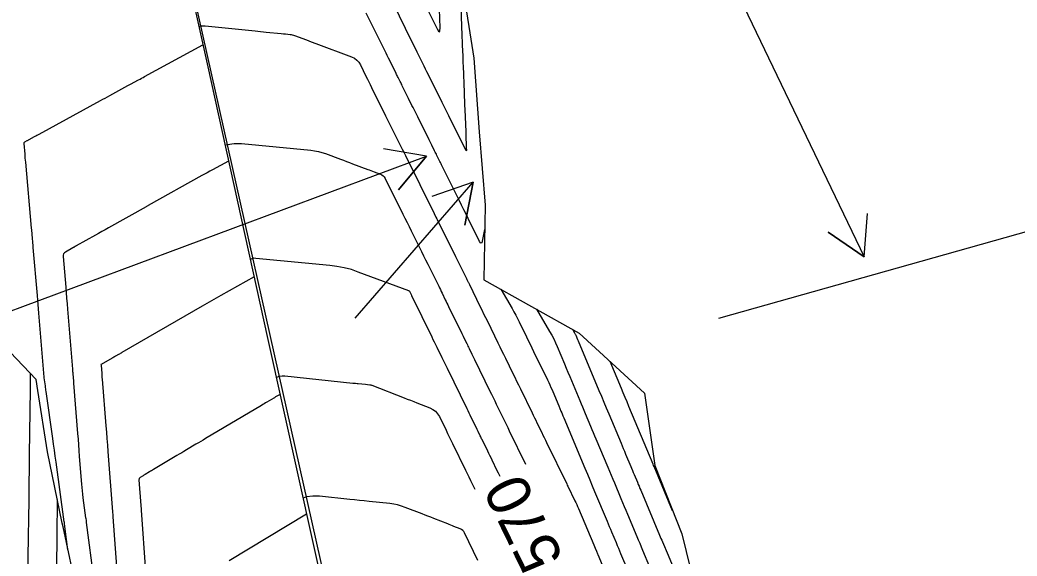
# Model space of a CAD drawing. Extents: x 954385 to 988206, y 1868364 to 1924553.
# Drawn here: x 957911.1 to 958048.1, y 1919236.3 to 1919309.9 of the extents above; entities that cross this region are included whole.
import ezdxf

# ---------------------------------------------------------------- set-up
doc = ezdxf.new("R2010")
doc.units = 0
for name, color, linetype in [('Default', 7, 'Continuous'), ('Ex_Contour Labels', 7, 'Continuous'), ('Ex_Major Contours', 7, 'Continuous'), ('Ex_Minor Contours', 7, 'Continuous'), ('Perimeter', 7, 'Continuous'), ('Proposed Cut', 7, 'Continuous'), ('Proposed Fill', 7, 'Continuous'), ('Slopes', 7, 'Continuous')]:
    doc.layers.add(name, color=color, linetype=linetype)

msp = doc.modelspace()

# ---------------------------------------------------------------- linework, layer by layer
for points in [[(957917.69, 1919237.11), (957917.27, 1919240.31), (957917.26, 1919240.36), (957917.21, 1919240.72), (957917.2, 1919240.78), (957917.2, 1919240.84), (957917.19, 1919240.91), (957917.18, 1919240.97), (957916.06, 1919249.16), (957915.94, 1919249.97), (957915.83, 1919250.78), (957915.72, 1919251.6), (957915.6, 1919252.41), (957914.69, 1919258.86), (957914.66, 1919259.05), (957914.64, 1919259.23), (957914.61, 1919259.42), (957914.58, 1919259.61), (957914.42, 1919260.74), (957914.41, 1919260.8), (957914.41, 1919260.81), (957914.41, 1919260.82), (957914.41, 1919260.83), (957914.41, 1919260.84), (957913.7, 1919269.6), (957913.65, 1919270.2), (957913.6, 1919270.81), (957913.55, 1919271.41), (957913.5, 1919272.02), (957912.93, 1919278.64), (957912.93, 1919278.69), (957912.92, 1919278.75), (957912.92, 1919278.8), (957912.91, 1919278.85), (957912.77, 1919280.44), (957912.75, 1919280.65), (957912.74, 1919280.86), (957912.72, 1919281.07), (957912.7, 1919281.28), (957911.88, 1919290.36), (957911.86, 1919290.63), (957911.83, 1919290.9), (957911.81, 1919291.17), (957911.79, 1919291.44), (957911.66, 1919292.91), (957911.66, 1919292.99), (957911.68, 1919293.05), (957911.72, 1919293.11), (957911.78, 1919293.15), (957912.07, 1919293.31), (957912.14, 1919293.35), (957912.21, 1919293.38), (957912.28, 1919293.42), (957912.35, 1919293.46), (957913.11, 1919293.88), (957913.26, 1919293.96), (957913.41, 1919294.05), (957913.56, 1919294.13), (957913.71, 1919294.21), (957922.16, 1919298.81), (957922.48, 1919298.99), (957922.79, 1919299.16), (957923.11, 1919299.33), (957923.42, 1919299.5), (957925.9, 1919300.87), (957926, 1919300.92), (957926.1, 1919300.97), (957926.2, 1919301.03), (957926.3, 1919301.08), (957927.38, 1919301.66), (957927.59, 1919301.77), (957927.8, 1919301.89), (957928.01, 1919302), (957928.22, 1919302.12), (957936.23, 1919306.49)], [(957939.75, 1919290.51), (957937.56, 1919289.31), (957937.19, 1919289.11), (957936.82, 1919288.91), (957936.46, 1919288.71), (957936.09, 1919288.51), (957928.72, 1919284.39), (957928.67, 1919284.37), (957928.49, 1919284.27), (957928.41, 1919284.22), (957923.25, 1919281.33), (957922.8, 1919281.08), (957922.35, 1919280.83), (957921.9, 1919280.57), (957921.45, 1919280.32), (957918.81, 1919278.84), (957918.78, 1919278.82), (957918.74, 1919278.8), (957918.71, 1919278.78), (957918.67, 1919278.75), (957918.52, 1919278.67), (957918.49, 1919278.65), (957918.45, 1919278.63), (957918.42, 1919278.61), (957918.38, 1919278.59), (957917.35, 1919278.01), (957917.19, 1919277.89), (957917.08, 1919277.75), (957917.03, 1919277.58), (957917.02, 1919277.38), (957917.38, 1919273.2), (957917.44, 1919272.44), (957917.51, 1919271.67), (957917.57, 1919270.9), (957917.63, 1919270.14), (957918.3, 1919261.93), (957918.31, 1919261.77), (957918.32, 1919261.61), (957918.34, 1919261.45), (957918.35, 1919261.29), (957918.43, 1919260.27), (957918.44, 1919260.14), (957918.44, 1919260.08), (957918.45, 1919260.01), (957919.01, 1919253.1), (957919.07, 1919252.31), (957919.13, 1919251.52), (957919.19, 1919250.73), (957919.25, 1919249.94), (957919.55, 1919246.12), (957919.59, 1919245.66), (957919.63, 1919245.19), (957919.68, 1919244.73), (957919.74, 1919244.27), (957920.12, 1919241.52), (957920.13, 1919241.47), (957920.18, 1919241.07), (957920.19, 1919241.02), (957920.2, 1919240.97), (957920.2, 1919240.91), (957920.21, 1919240.86), (957921.26, 1919232.87)], [(957943.26, 1919274.6), (957938.68, 1919272.02), (957938.04, 1919271.66), (957937.41, 1919271.3), (957936.77, 1919270.93), (957936.13, 1919270.57), (957925.09, 1919264.2), (957924.98, 1919264.13), (957924.87, 1919264.07), (957924.76, 1919264), (957924.65, 1919263.94), (957924.2, 1919263.69), (957924.09, 1919263.62), (957923.98, 1919263.56), (957923.87, 1919263.49), (957923.76, 1919263.43), (957922.24, 1919262.55), (957922.23, 1919262.54), (957922.23, 1919262.54), (957922.22, 1919262.54), (957922.23, 1919262.46), (957922.32, 1919261.32), (957922.33, 1919261.13), (957922.35, 1919260.94), (957922.36, 1919260.76), (957922.38, 1919260.57), (957922.9, 1919254.15), (957922.97, 1919253.26), (957923.04, 1919252.38), (957923.11, 1919251.5), (957923.17, 1919250.62), (957923.81, 1919242.33), (957923.81, 1919242.29), (957923.84, 1919241.89), (957923.85, 1919241.83), (957923.85, 1919241.77), (957923.85, 1919241.72), (957923.86, 1919241.66), (957924.48, 1919232.92)], [(957946.83, 1919258.46), (957946.31, 1919258.16), (957946.22, 1919258.11), (957946.14, 1919258.06), (957946.05, 1919258), (957945.96, 1919257.95), (957945.02, 1919257.39), (957944.83, 1919257.28), (957944.64, 1919257.17), (957944.46, 1919257.06), (957944.27, 1919256.95), (957936.59, 1919252.39), (957936.26, 1919252.19), (957935.93, 1919252), (957935.6, 1919251.8), (957935.27, 1919251.61), (957933.96, 1919250.82), (957933.63, 1919250.62), (957933.31, 1919250.43), (957932.98, 1919250.23), (957932.65, 1919250.04), (957929.44, 1919248.13), (957929.31, 1919248.05), (957929.18, 1919247.97), (957929.05, 1919247.89), (957928.91, 1919247.81), (957928.3, 1919247.44), (957928.21, 1919247.39), (957928.12, 1919247.34), (957928.04, 1919247.29), (957927.95, 1919247.23), (957927.6, 1919247.03), (957927.53, 1919246.97), (957927.48, 1919246.9), (957927.45, 1919246.82), (957927.44, 1919246.72), (957927.71, 1919243.2), (957927.72, 1919243.15), (957927.75, 1919242.75), (957927.75, 1919242.69), (957927.75, 1919242.64), (957927.76, 1919242.59), (957927.76, 1919242.54), (957928.36, 1919234.15)], [(957939.85, 1919235.64), (957950.47, 1919242.04)]]:
    msp.add_lwpolyline(points)
at = {"layer": 'Default'}
msp.add_line((958200.6, 1918129.72), (957843.86, 1919719.4), dxfattribs=at)
at = {"layer": 'Ex_Major Contours'}
for points in [[(957966.83, 1919311.87), (957968.4, 1919308.69), (957968.6, 1919308.36), (957968.73, 1919308.26), (957968.8, 1919308.41), (957968.81, 1919308.8), (957968.71, 1919311.35)], [(957977.06, 1919247.16), (957977.01, 1919247.28), (957976.84, 1919247.62), (957976.67, 1919247.97), (957975.96, 1919249.43), (957975.81, 1919249.73), (957975.66, 1919250.04), (957975.51, 1919250.35), (957975.36, 1919250.66), (957974.59, 1919252.25), (957974.52, 1919252.37), (957974.46, 1919252.5), (957974.4, 1919252.62), (957974.34, 1919252.75), (957974.04, 1919253.37), (957973.91, 1919253.62), (957973.85, 1919253.75), (957973.1, 1919255.28), (957972.96, 1919255.58), (957972.81, 1919255.88), (957972.67, 1919256.18), (957972.52, 1919256.47), (957969.82, 1919262.02), (957969.64, 1919262.38), (957969.47, 1919262.74), (957969.29, 1919263.1), (957969.11, 1919263.46), (957968.41, 1919264.89), (957968.23, 1919265.25), (957968.06, 1919265.61), (957967.88, 1919265.97), (957967.71, 1919266.33), (957964.97, 1919271.92), (957964.96, 1919271.95), (957964.95, 1919271.97), (957964.94, 1919272), (957964.93, 1919272.02), (957964.83, 1919272.22), (957964.68, 1919272.52), (957964.65, 1919272.57), (957964.6, 1919272.62), (957964.56, 1919272.65), (957964.5, 1919272.68), (957957.57, 1919275.26), (957956.62, 1919275.59), (957955.64, 1919275.85), (957954.65, 1919276.04), (957953.65, 1919276.17), (957943.49, 1919277.13), (957943.18, 1919277.16), (957943.14, 1919277.16), (957943.11, 1919277.16), (957943.07, 1919277.15), (957943.04, 1919277.13), (957942.78, 1919276.97), (957942.74, 1919276.95)], [(957987, 1919267.41), (957987.28, 1919266.92), (957987.33, 1919266.84), (957987.38, 1919266.75), (957987.42, 1919266.67), (957987.45, 1919266.58), (957987.69, 1919266.01), (957987.77, 1919265.83), (957990.64, 1919258.98), (957990.97, 1919258.19), (957991.31, 1919257.39), (957991.64, 1919256.59), (957991.98, 1919255.79), (957993.67, 1919251.76), (957993.83, 1919251.38), (957993.98, 1919251.01), (957994.14, 1919250.64), (957994.3, 1919250.26), (957995.01, 1919248.57), (957995.12, 1919248.3), (957995.24, 1919248.02), (957995.35, 1919247.75), (957995.47, 1919247.47), (957995.93, 1919246.38), (957996.04, 1919246.1), (957996.16, 1919245.83), (957996.27, 1919245.55), (957996.39, 1919245.28), (957998.97, 1919239.11), (957999.07, 1919238.88), (957999.16, 1919238.65), (957999.26, 1919238.43), (957999.36, 1919238.2), (958000.13, 1919236.37), (958003.01, 1919229.5)], [(957916.22, 1919244.01), (957916.16, 1919238.96), (957916.16, 1919238.7), (957916.15, 1919238.44), (957916.15, 1919238.18), (957916.15, 1919237.92), (957916.09, 1919233.61)]]:
    msp.add_lwpolyline(points, dxfattribs=at)
at = {"layer": 'Ex_Minor Contours'}
for points in [[(957971.55, 1919314.29), (957971.81, 1919307.77), (957971.82, 1919307.42), (957971.84, 1919307.07), (957971.85, 1919306.72), (957971.86, 1919306.37), (957971.92, 1919304.98), (957971.93, 1919304.64), (957971.95, 1919304.29), (957971.96, 1919303.94), (957971.98, 1919303.59), (957972.12, 1919299.94), (957972.14, 1919299.36), (957972.16, 1919298.77), (957972.19, 1919298.19), (957972.21, 1919297.61), (957972.33, 1919294.52), (957972.34, 1919294.32), (957972.34, 1919294.13), (957972.35, 1919293.93), (957972.36, 1919293.74), (957972.4, 1919292.76), (957972.41, 1919292.57), (957972.41, 1919292.39), (957972.43, 1919292.01), (957972.43, 1919291.94), (957972.41, 1919291.91), (957972.39, 1919291.93), (957972.35, 1919291.99), (957970.01, 1919296.71), (957969.78, 1919297.18), (957969.54, 1919297.64), (957969.31, 1919298.11), (957969.08, 1919298.57), (957967.2, 1919302.36), (957967.01, 1919302.75), (957966.82, 1919303.14), (957966.62, 1919303.52), (957966.43, 1919303.91), (957965.66, 1919305.47), (957965.28, 1919306.25), (957964.89, 1919307.02), (957962.39, 1919312.08)], [(957974.93, 1919281.09), (957974.6, 1919279.49), (957974.54, 1919279.29), (957974.46, 1919279.21), (957974.36, 1919279.26), (957974.25, 1919279.44), (957972.68, 1919282.6), (957972.38, 1919283.21), (957972.08, 1919283.82), (957971.77, 1919284.43), (957971.47, 1919285.04), (957969.01, 1919289.98), (957968.94, 1919290.14), (957968.86, 1919290.3), (957968.78, 1919290.46), (957968.7, 1919290.62), (957968.38, 1919291.27), (957968.3, 1919291.43), (957968.22, 1919291.59), (957968.14, 1919291.75), (957968.06, 1919291.91), (957967.67, 1919292.68), (957967.49, 1919293.04), (957967.31, 1919293.4), (957966.38, 1919295.28), (957966.22, 1919295.6), (957966.06, 1919295.92), (957965.9, 1919296.24), (957965.74, 1919296.56), (957965.11, 1919297.84), (957964.95, 1919298.16), (957964.79, 1919298.48), (957964.63, 1919298.8), (957964.47, 1919299.12), (957963.61, 1919300.86), (957963.54, 1919301), (957963.47, 1919301.14), (957963.4, 1919301.28), (957963.33, 1919301.42), (957963.05, 1919301.98), (957962.98, 1919302.12), (957962.91, 1919302.26), (957962.84, 1919302.4), (957962.78, 1919302.54), (957961.9, 1919304.31), (957961.73, 1919304.65), (957961.56, 1919304.99), (957961.39, 1919305.33), (957961.23, 1919305.67), (957958.68, 1919310.82)], [(957935.68, 1919308.98), (957935.68, 1919308.98), (957935.95, 1919309.06), (957936.23, 1919309.1), (957936.52, 1919309.09), (957943.39, 1919308.38), (957943.78, 1919308.34), (957944.16, 1919308.3), (957944.55, 1919308.26), (957944.94, 1919308.23), (957946.97, 1919308.03), (957947.28, 1919308), (957947.59, 1919307.97), (957948.21, 1919307.91), (957948.36, 1919307.89), (957948.51, 1919307.86), (957948.66, 1919307.82), (957948.8, 1919307.77), (957950.45, 1919307.15), (957951.09, 1919306.9), (957951.74, 1919306.66), (957956.66, 1919304.8), (957957.04, 1919304.62), (957957.36, 1919304.38), (957957.64, 1919304.08), (957957.86, 1919303.72), (957958.62, 1919302.16), (957958.82, 1919301.77), (957959.01, 1919301.38), (957959.2, 1919301), (957959.4, 1919300.61), (957961.33, 1919296.72), (957961.55, 1919296.26), (957961.78, 1919295.81), (957962.01, 1919295.35), (957962.23, 1919294.9), (957963.14, 1919293.07), (957963.36, 1919292.62), (957963.59, 1919292.16), (957963.82, 1919291.71), (957964.04, 1919291.25), (957968, 1919283.3), (957968.19, 1919282.91), (957968.24, 1919282.8), (957968.35, 1919282.59), (957968.4, 1919282.48), (957969.93, 1919279.41), (957970.18, 1919278.91), (957970.43, 1919278.4), (957970.68, 1919277.9), (957970.93, 1919277.4), (957972.34, 1919274.55), (957972.43, 1919274.38), (957972.51, 1919274.22), (957972.67, 1919273.89), (957972.71, 1919273.81), (957972.76, 1919273.72), (957972.8, 1919273.64), (957972.84, 1919273.56), (957974.29, 1919270.59), (957974.54, 1919270.07), (957974.8, 1919269.54), (957975.05, 1919269.02), (957975.31, 1919268.5), (957976.76, 1919265.54), (957977.01, 1919265.01), (957977.27, 1919264.49), (957977.53, 1919263.96), (957977.78, 1919263.44), (957978.81, 1919261.33), (957979.07, 1919260.81), (957979.32, 1919260.28), (957979.58, 1919259.76), (957979.84, 1919259.23), (957981.45, 1919255.93), (957981.61, 1919255.59), (957981.78, 1919255.25), (957981.95, 1919254.91), (957982.11, 1919254.57), (957982.78, 1919253.2), (957982.94, 1919252.86), (957983.11, 1919252.52), (957983.28, 1919252.18), (957983.44, 1919251.84), (957986.21, 1919246.17), (957986.29, 1919246.01), (957986.36, 1919245.86), (957987.34, 1919243.85), (957987.47, 1919243.59), (957987.59, 1919243.33), (957987.7, 1919243.07), (957987.82, 1919242.8), (957989.92, 1919237.79), (957990.01, 1919237.57), (957990.1, 1919237.35), (957990.29, 1919236.9), (957990.34, 1919236.79), (957990.38, 1919236.68), (957990.43, 1919236.57), (957990.47, 1919236.46), (957993.42, 1919229.47)], [(957939.27, 1919292.68), (957939.6, 1919292.78), (957940.54, 1919292.92), (957941.51, 1919292.9), (957951.07, 1919291.99), (957951.58, 1919291.92), (957952.09, 1919291.83), (957952.58, 1919291.7), (957953.06, 1919291.53), (957955.12, 1919290.76), (957955.54, 1919290.61), (957955.96, 1919290.45), (957956.38, 1919290.29), (957956.8, 1919290.14), (957958.87, 1919289.36), (957959.09, 1919289.28), (957959.3, 1919289.2), (957959.52, 1919289.12), (957959.74, 1919289.04), (957960.61, 1919288.71), (957960.82, 1919288.62), (957960.99, 1919288.49), (957961.14, 1919288.33), (957961.26, 1919288.13), (957963.7, 1919283.21), (957963.99, 1919282.64), (957964.27, 1919282.07), (957964.55, 1919281.5), (957964.84, 1919280.92), (957965.97, 1919278.64), (957966.26, 1919278.07), (957966.54, 1919277.5), (957966.82, 1919276.93), (957967.11, 1919276.36), (957968.62, 1919273.31), (957968.74, 1919273.08), (957968.85, 1919272.85), (957968.96, 1919272.61), (957969.08, 1919272.38), (957969.53, 1919271.45), (957969.65, 1919271.22), (957969.76, 1919270.99), (957969.87, 1919270.76), (957969.99, 1919270.52), (957971.81, 1919266.8), (957971.98, 1919266.46), (957972.14, 1919266.12), (957972.48, 1919265.44), (957972.56, 1919265.27), (957972.64, 1919265.1), (957972.72, 1919264.93), (957972.81, 1919264.76), (957973.19, 1919263.98), (957973.28, 1919263.8), (957973.37, 1919263.61), (957973.46, 1919263.43), (957973.55, 1919263.24), (957975.66, 1919258.92), (957975.88, 1919258.47), (957976.1, 1919258.01), (957976.32, 1919257.56), (957976.54, 1919257.1), (957977.43, 1919255.28), (957977.65, 1919254.83), (957977.88, 1919254.37), (957978.1, 1919253.92), (957978.32, 1919253.47), (957980.56, 1919248.87)], [(957977.14, 1919272.89), (957978.7, 1919270.25), (957978.95, 1919269.8), (957979.2, 1919269.36), (957979.44, 1919268.9), (957979.67, 1919268.44), (957980.69, 1919266.36), (957980.93, 1919265.86), (957981.17, 1919265.36), (957981.42, 1919264.86), (957981.66, 1919264.36), (957983.58, 1919260.44), (957983.74, 1919260.1), (957983.9, 1919259.76), (957984.05, 1919259.42), (957984.2, 1919259.07), (957984.98, 1919257.2), (957985.12, 1919256.87), (957985.42, 1919256.16), (957985.52, 1919255.91), (957985.7, 1919255.49), (957985.77, 1919255.32), (957985.8, 1919255.24), (957988.71, 1919248.3), (957989.05, 1919247.51), (957989.38, 1919246.71), (957989.72, 1919245.91), (957990.05, 1919245.11), (957991.75, 1919241.06), (957991.9, 1919240.69), (957992.06, 1919240.32), (957992.22, 1919239.95), (957992.37, 1919239.57), (957993, 1919238.09), (957993.15, 1919237.71), (957993.31, 1919237.34), (957993.47, 1919236.97), (957993.62, 1919236.6), (957995.46, 1919232.23)], [(957982.07, 1919270.15), (957983.86, 1919267.11), (957984.15, 1919266.6), (957984.42, 1919266.08), (957984.67, 1919265.55), (957984.91, 1919265.02), (957985.9, 1919262.65), (957986.14, 1919262.07), (957986.38, 1919261.5), (957986.62, 1919260.92), (957986.87, 1919260.35), (957988.01, 1919257.61), (957988.2, 1919257.17), (957988.38, 1919256.73), (957988.57, 1919256.29), (957988.75, 1919255.85), (957989.49, 1919254.09), (957989.67, 1919253.65), (957989.86, 1919253.21), (957990.04, 1919252.77), (957990.23, 1919252.33), (957991.86, 1919248.44), (957992.08, 1919247.9), (957992.31, 1919247.36), (957992.53, 1919246.83), (957992.76, 1919246.29), (957993.66, 1919244.15), (957993.88, 1919243.61), (957994.11, 1919243.07), (957994.33, 1919242.54), (957994.56, 1919242), (957995.85, 1919238.92), (957996.04, 1919238.46), (957996.24, 1919238), (957996.43, 1919237.53), (957996.63, 1919237.07), (957997.6, 1919234.76)], [(958000.76, 1919242.48), (957998.22, 1919248.55), (957998.15, 1919248.7), (957998.09, 1919248.85), (957994.75, 1919256.81), (957994.5, 1919257.43), (957994.24, 1919258.05), (957993.98, 1919258.66), (957993.72, 1919259.28), (957992.16, 1919262.99)], [(957912.19, 1919233), (957912.27, 1919238.97), (957912.27, 1919239.31), (957912.28, 1919239.65), (957912.28, 1919240), (957912.29, 1919240.34), (957912.4, 1919249.54), (957912.4, 1919249.9), (957912.41, 1919249.99), (957912.41, 1919250.22), (957912.53, 1919259.13), (957912.53, 1919259.67), (957912.54, 1919260.21), (957912.55, 1919260.75), (957912.56, 1919261.29), (957912.56, 1919261.31)], [(957946.31, 1919260.8), (957946.4, 1919260.84), (957946.74, 1919260.95), (957947.1, 1919261), (957947.47, 1919260.99), (957956.84, 1919260.02), (957957.02, 1919260.01), (957957.21, 1919259.99), (957957.4, 1919259.97), (957957.58, 1919259.95), (957958.55, 1919259.85), (957958.86, 1919259.81), (957959.16, 1919259.78), (957959.23, 1919259.77), (957959.31, 1919259.76), (957959.38, 1919259.74), (957959.45, 1919259.71), (957963.87, 1919257.99), (957964.31, 1919257.81), (957964.76, 1919257.64), (957965.2, 1919257.47), (957965.64, 1919257.3), (957967.41, 1919256.61), (957967.82, 1919256.4), (957968.18, 1919256.13), (957968.47, 1919255.8), (957968.71, 1919255.41), (957969.63, 1919253.53), (957969.85, 1919253.08), (957970.07, 1919252.62), (957970.29, 1919252.17), (957970.52, 1919251.71), (957972.3, 1919248.05), (957972.53, 1919247.58), (957972.76, 1919247.12), (957972.99, 1919246.65), (957973.21, 1919246.18), (957973.57, 1919245.46)], [(957974.02, 1919235.64), (957972.18, 1919239.42), (957972.07, 1919239.61), (957971.93, 1919239.77), (957971.76, 1919239.9), (957971.56, 1919240), (957970.71, 1919240.33), (957970.5, 1919240.41), (957970.29, 1919240.49), (957970.08, 1919240.58), (957969.87, 1919240.66), (957967.94, 1919241.41), (957967.54, 1919241.57), (957967.15, 1919241.72), (957966.76, 1919241.87), (957966.37, 1919242.03), (957964.03, 1919242.93), (957963.51, 1919243.12), (957962.98, 1919243.27), (957962.44, 1919243.38), (957961.89, 1919243.46), (957959.05, 1919243.75), (957958.39, 1919243.82), (957957.73, 1919243.89), (957957.07, 1919243.96), (957956.41, 1919244.03), (957952.23, 1919244.46), (957951.33, 1919244.49), (957950.47, 1919244.37), (957949.99, 1919244.22)]]:
    msp.add_lwpolyline(points, dxfattribs=at)
at = {"layer": 'Perimeter'}
for points in [[(957910.49, 1919421.74), (957920, 1919379.49), (957928.68, 1919340.64), (957936.81, 1919303.87), (957945.16, 1919266), (957953.4, 1919228.82)], [(957950.26, 1919401.91), (957951.58, 1919391.96), (957954.19, 1919382.29), (957956.96, 1919372.67), (957961.23, 1919363.38), (957964.4, 1919353.84), (957966.1, 1919344.99), (957968.06, 1919334.16), (957970.2, 1919324.39), (957971.9, 1919314.53), (957973.45, 1919304.62), (957974.2, 1919294.54), (957974.99, 1919284.47), (957974.82, 1919274.19), (957987.94, 1919266.88), (957996.88, 1919258.64), (957998.3, 1919248.71), (958002.02, 1919239.29), (958004.43, 1919229.59)], [(957919.01, 1919231), (957917.01, 1919240.26), (957916.9, 1919240.78), (957914.86, 1919250.57), (957913.54, 1919258.99), (957913.34, 1919260.51), (957905.2, 1919268.95)]]:
    msp.add_lwpolyline(points, dxfattribs=at)
at = {"layer": 'Proposed Cut'}
msp.add_lwpolyline([(957913.34, 1919260.51), (957905.2, 1919268.95), (957901.47, 1919276.22), (957900.45, 1919278.15), (957895.68, 1919287.34), (957892.38, 1919294.08), (957891.08, 1919296.54), (957886.89, 1919305.86), (957884.81, 1919311.67), (957883.53, 1919315.36), (957879.3, 1919324.66), (957877.21, 1919329.27), (957875.44, 1919333.92), (957871.95, 1919343.39), (957870.15, 1919347.96), (957868.24, 1919352.81), (957864.59, 1919362.24), (957862.78, 1919366.71), (957860.74, 1919371.53), (957856.68, 1919380.86), (957854.25, 1919386.89), (957852.72, 1919390.22), (957848.14, 1919399.44)], dxfattribs=at)
at = {"layer": 'Proposed Fill'}
msp.add_lwpolyline([(957937.99, 1919144.23), (957936.12, 1919152.9), (957934.67, 1919159.76), (957934.04, 1919162.68), (957931.82, 1919172.43), (957930.09, 1919179.85), (957929.57, 1919182.18), (957927.35, 1919191.93), (957925.3, 1919200.72), (957925.06, 1919201.66), (957922.64, 1919211.37), (957920.8, 1919221.2), (957920.73, 1919221.63), (957919.01, 1919231), (957917.01, 1919240.26), (957916.9, 1919240.78), (957914.86, 1919250.57), (957913.54, 1919258.99), (957913.34, 1919260.51)], dxfattribs=at)
at = {"layer": 'Slopes'}
for points in [[(958007.13, 1919318.93), (958027.06, 1919277.33), (958022.11, 1919280.72), (958027.06, 1919277.33), (958027.52, 1919283.31)], [(957907.13, 1919268.93), (957966.95, 1919291.17), (957963.12, 1919286.54), (957966.95, 1919291.17), (957961.03, 1919292.17)], [(957957.13, 1919268.93), (957973.35, 1919287.59), (957972.2, 1919281.7), (957973.35, 1919287.59), (957967.67, 1919285.64)], [(958007.13, 1919268.93), (958061.22, 1919284.17), (958057.03, 1919279.87), (958061.22, 1919284.17), (958055.41, 1919285.65)]]:
    msp.add_lwpolyline(points, dxfattribs=at)

# ---------------------------------------------------------------- texts
at = {"layer": 'Ex_Contour Labels'}
msp.add_text('570', height=6, rotation=116.0131, dxfattribs=at).set_placement((957985.87, 1919235.96))

doc.saveas('drawing.dxf')
